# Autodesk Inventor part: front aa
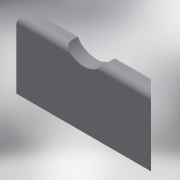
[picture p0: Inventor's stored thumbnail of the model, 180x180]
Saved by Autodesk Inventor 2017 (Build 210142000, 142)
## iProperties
Created: 2017-11
Part Number: front aa
Material: Generic
Document SubType Name: Modeling
Designer: lshopper
Density: 1 g/cm^3
Appearance: Default
Author: lshopper
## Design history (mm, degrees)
sketch "Sketch1"
  geometry: L1 (101.6, 16.803)-(-101.6, 16.803); L2 (-101.6, 16.803)-(-82.55, -2.247); L3 (-82.55, -2.247)-(82.55, -2.247); L4 (82.55, -2.247)-(101.6, 16.803); 2 further points
  constraints: 8 end point, 1 horizontal, 1 midpoint, 1 parallel, 1 vertical alignment
  dimensions: "d0" = 19.05 distance between parallel lines of L3 L1; "d1" = 203.2 distance of L1.start L1.end; "d2" = 45 deg angle of L1 L4; "d3" = 45 deg angle of L1 L2
extrude "Extrusion1" new body sketch "Sketch1" distance "d4" = 101.6; taper "d5" = 0 deg
sketch "Sketch2"
  geometry: C1 r 33.558 at (101.6, 119.989); 1 further point
  constraints: 1 centre point
extrude "Extrusion2" cut sketch "Sketch2" distance "d6" = 101.6; taper "d7" = 0 deg
fillet "Fillet1" dims "d8" = 9.525
fillet "Fillet2" dims "d9" = 9.525
body "Solid1"
